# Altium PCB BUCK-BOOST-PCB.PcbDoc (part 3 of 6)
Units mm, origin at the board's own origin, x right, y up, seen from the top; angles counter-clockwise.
Board outline 99.9 x 67.48 mm, 4 copper layers (Top Layer, POWER, GND, Bottom Layer); 181 components, 110 nets, 560 pads, 389 vias.
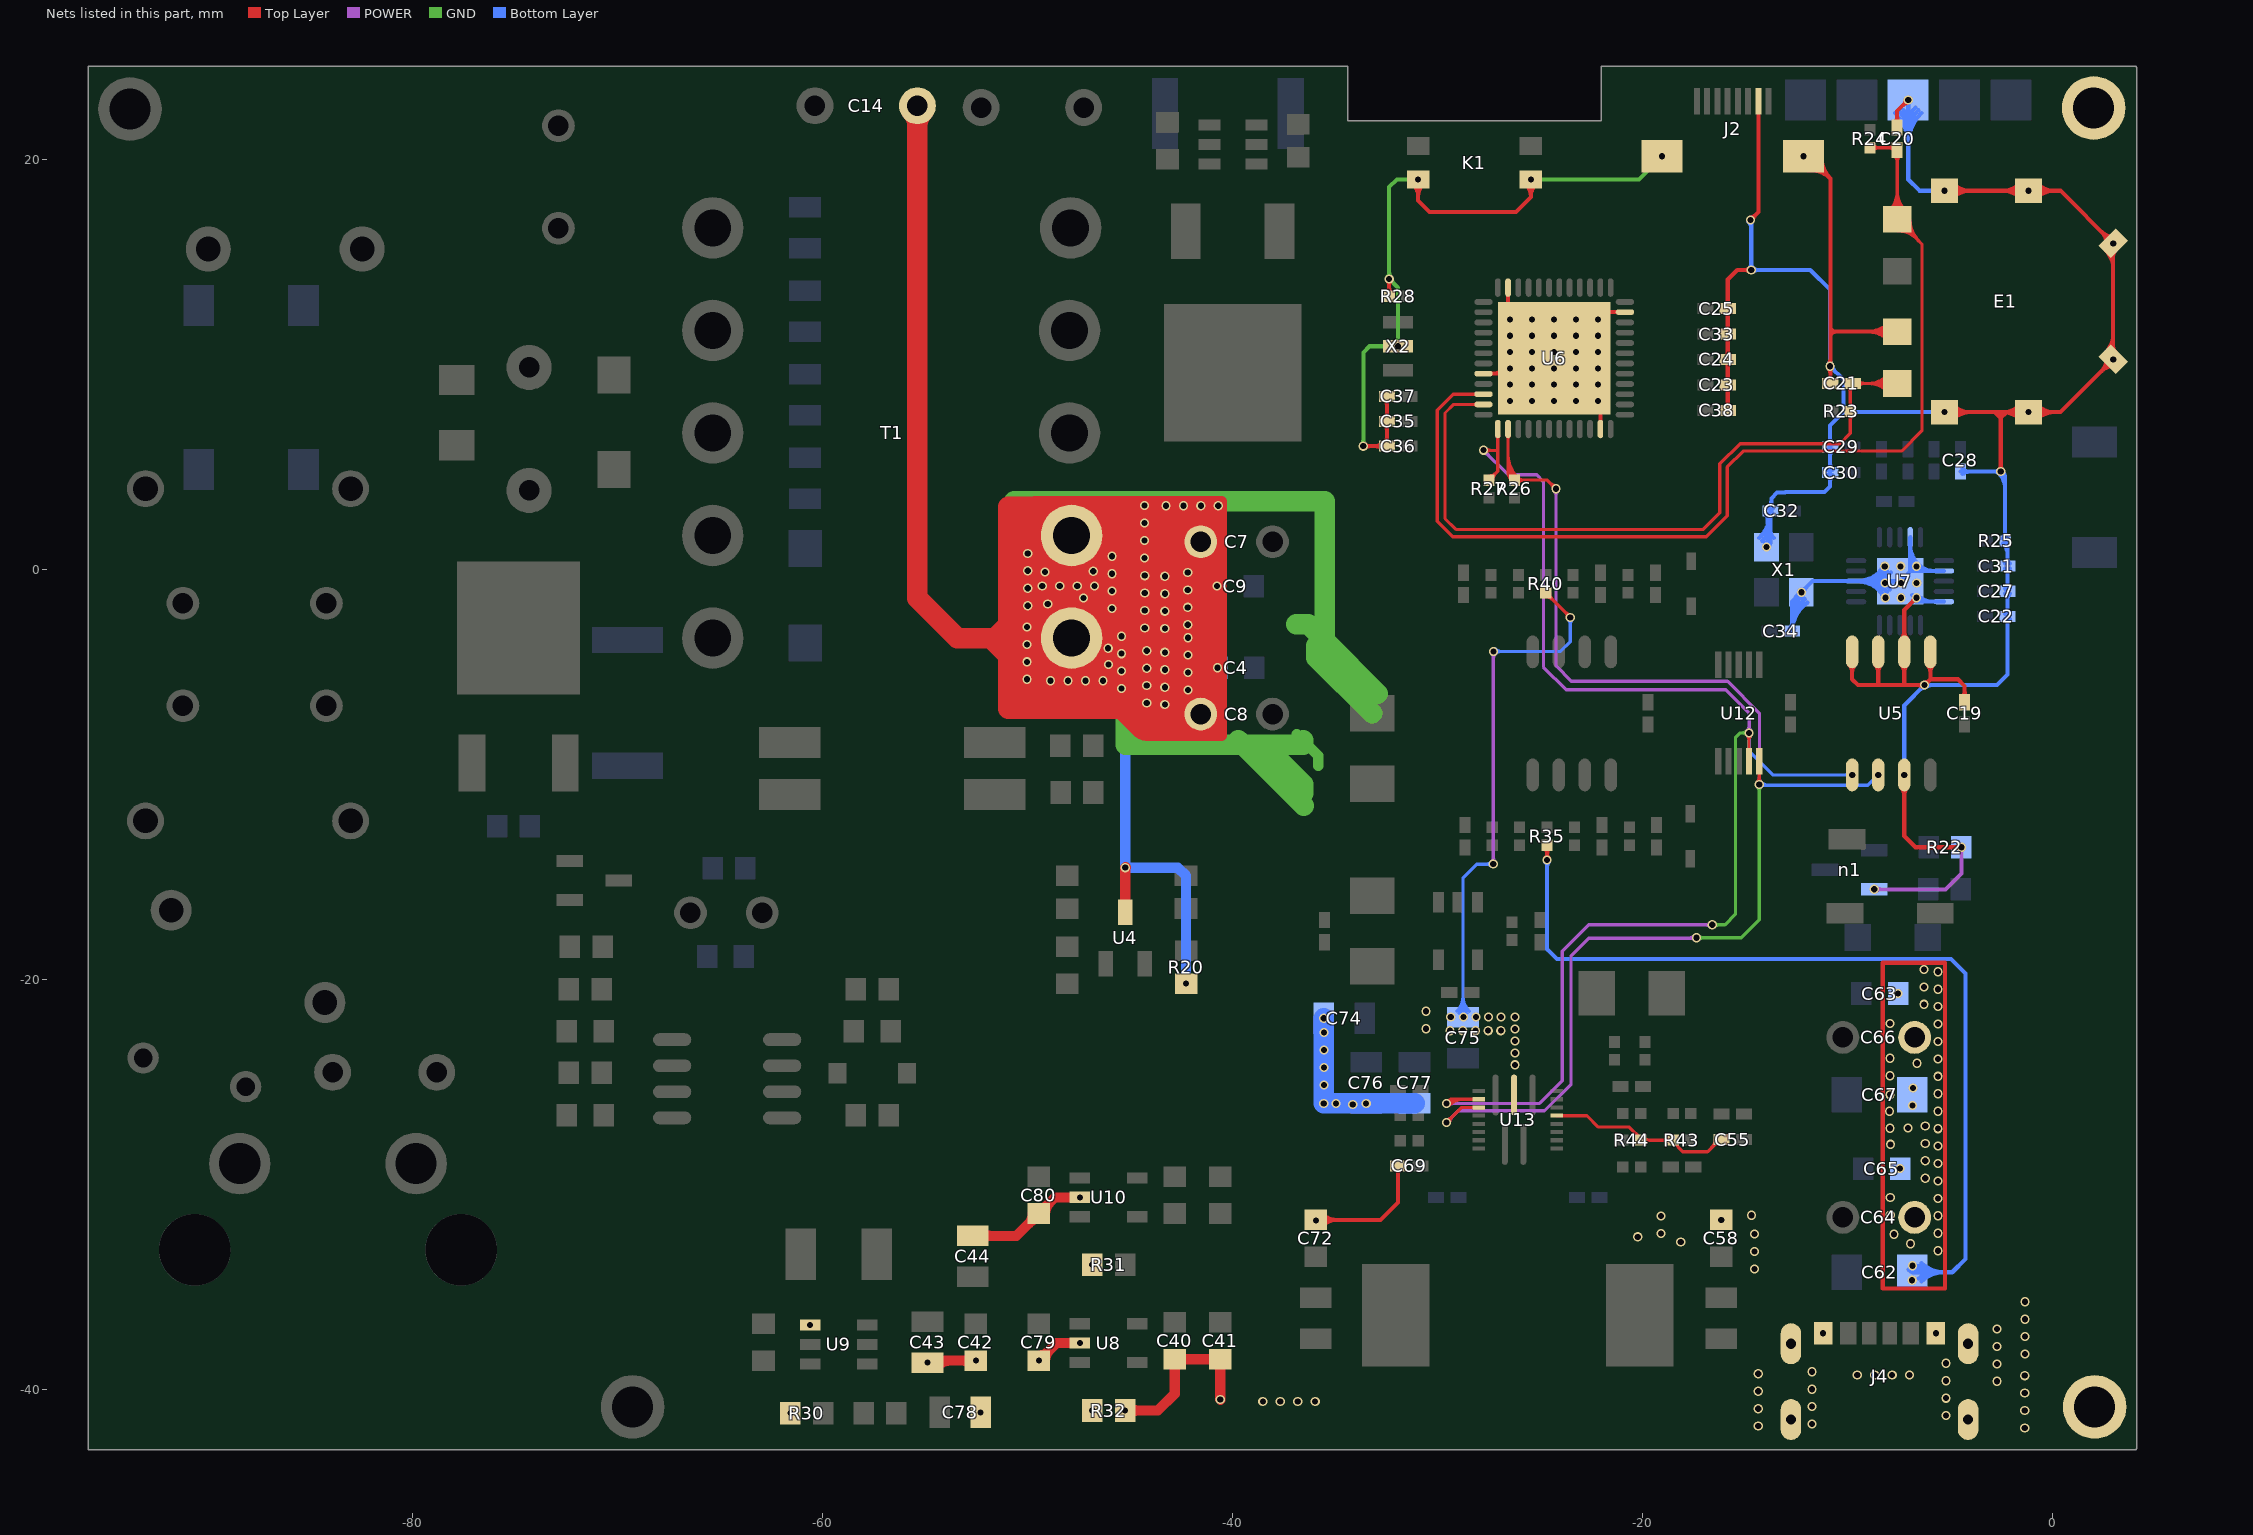
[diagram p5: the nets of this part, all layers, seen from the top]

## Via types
v1: diameter 0.45, hole 0.3, Top Layer to Bottom Layer, 389 vias

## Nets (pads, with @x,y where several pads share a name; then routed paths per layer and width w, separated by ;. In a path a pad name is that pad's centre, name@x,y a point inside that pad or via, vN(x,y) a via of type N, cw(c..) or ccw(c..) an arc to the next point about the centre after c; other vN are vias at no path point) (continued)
DGND: C19.2 C20.2 C21.2 C22.1 C23.1 C24.1 C25.1 C27.1 C28.1 C29.2 C30.2 C31.1 C32.2 C33.2 C34.2 C35.2 C36.2 C37.1 C38.2 C40.2 C41.2 E1.1 E1.2 E1.3 E1.4 E1.5 E1.6 E1.C J2.2 J2.9 J2.10 K1.3 K1.4 n1.2 pad.2 pad.@2.014,22.522 R22.2 R25.2 R28.1 R32.1 U5.1 U5.2 U5.3 U5.4 U5.7 U6.8 U6.23 U6.35 U6.47 U6.49 U7.8 U7.14 U7.17 U7.20 U7.21 X1.2 X1.4 X2.3 | length 361
  Top Layer w0.2: v1@-33.612,6.034 v1(-33.607,6.029) C36.2@-32.459,6.029 C35.2@-32.459,7.233 C37.1@-32.459,8.456 ; v1@-33.519,5.941 cw(c-33.305,5.727) -33.305,6.029 cw(c-33.305,6.331) v1@-33.519,6.117 ; C36.2@-32.705,5.909 ccw(c-32.995,5.619) -32.995,6.029 ccw(c-32.995,6.439) C36.2@-32.705,6.149 ; C36.2@-32.58,6.149 ccw(c-32.87,6.439) -32.459,6.439 ccw(c-32.049,6.439) C36.2@-32.339,6.149 ; C35.2@-32.58,7.113 cw(c-32.87,6.823) -32.459,6.823 cw(c-32.049,6.823) C35.2@-32.339,7.113 ; C35.2@-32.58,7.353 ccw(c-32.87,7.643) -32.459,7.643 ccw(c-32.049,7.643) C35.2@-32.339,7.353 ; C37.1@-32.58,8.336 cw(c-32.87,8.046) -32.459,8.046 cw(c-32.049,8.046) C37.1@-32.339,8.336 ; R28.1@-32.467,13.459 ccw(c-32.758,13.75) -32.347,13.75 ccw(c-31.937,13.75) R28.1@-32.227,13.459 ; v1@-32.436,14.099 cw(c-32.649,13.886) -32.347,13.886 cw(c-32.045,13.886) v1@-32.259,14.099 ; v1@-32.361,14.201 v1(-32.347,14.187) R28.1@-32.347,13.339 ; K1.3@-31.173,18.801 cw(c-31.75,18.225) -30.935,18.225 cw(c-30.12,18.225) K1.3@-30.696,18.801 ; K1.3@-31.023,18.952 cw(c-31.237,18.738) -30.935,18.738 cw(c-30.633,18.738) K1.3@-30.846,18.952 ; v1(-30.935,19.04) -30.935,18.014 -30.375,17.454 -26.161,17.454 -25.435,18.18 v1(-25.435,19.04) ; U6.8@-27.746,9.564 -25.046,9.564 U6.49@-24.296,10.314 ; U6.8@-27.385,9.564 ccw(c-27.385,10.755) U6.49@-26.544,9.913 ; U6.49@-26.903,9.564 ccw(c-26.903,10.272) U6.49@-26.402,9.771 ; U6.47@-26.547,13.763 U6.49@-26.547,12.564 ; U6.49@-26.545,12.298 ccw(c-26.681,12.43) U6.49@-26.547,12.564 ; U6.49@-26.508,9.771 ccw(c-26.008,10.272) U6.49@-26.008,9.564 ; U6.49@-26.455,12.086 cw(c-26.455,11.153) U6.49@-25.796,11.813 ; U6.49@-26.455,12.286 cw(c-26.455,11.836) U6.49@-26.137,12.154 ; U6.49@-26.367,9.913 ccw(c-25.525,10.755) U6.49@-25.525,9.564 ; U6.49@-26.311,9.564 ccw(c-26.311,10.755) U6.49@-25.47,9.913 ; U6.49@-25.828,9.564 ccw(c-25.828,10.272) U6.49@-25.328,9.771 ; K1.4@-25.673,18.801 cw(c-26.249,18.225) -25.435,18.225 cw(c-24.62,18.225) K1.4@-25.196,18.801 ; U6.49@-25.624,11.641 ccw(c-25.381,11.884) U6.49@-25.381,11.541 ; U6.49@-25.583,11.6 cw(c-25.767,11.416) U6.49@-25.506,11.416 ; K1.4@-25.523,18.952 cw(c-25.736,18.738) -25.435,18.738 cw(c-25.133,18.738) K1.4@-25.346,18.952 ; U6.49@-25.381,11.291 cw(c-25.381,11.03) U6.49@-25.197,11.214 ; U6.49@-25.256,11.416 ccw(c-24.913,11.416) U6.49@-25.156,11.173 ; U6.49@-25.025,11.043 ccw(c-24.307,11.761) -24.307,10.745 ccw(c-24.307,11.813) U6.49@-23.552,11.058 ; U6.49@-24.745,9.865 ccw(c-25.5,10.62) U6.49@-24.432,10.62 ; U6.49@-24.684,10.701 ccw(c-24.307,11.078) -24.307,10.545 ccw(c-24.307,11.13) U6.49@-23.894,10.716 ; U6.49@-24.403,10.206 ccw(c-24.817,10.62) U6.49@-24.232,10.62 ; U6.49@-24.382,10.62 ccw(c-23.849,10.62) U6.49@-24.226,10.243 ; U6.49@-24.182,10.62 ccw(c-23.167,10.62) U6.49@-23.885,9.902 ; U6.49@-23.603,9.62 cw(c-24.194,9.029) U6.49@-23.358,9.029 ; U6.49@-23.474,11.136 ccw(c-23.753,11.416) U6.49@-23.358,11.416 ; U6.49@-23.38,11.23 cw(c-23.233,11.082) U6.49@-23.233,11.291 ; U6.49@-23.261,9.279 cw(c-23.511,9.029) U6.49@-23.158,9.029 ; U6.49@-23.233,8.904 cw(c-23.233,8.068) U6.49@-22.642,8.659 ; U6.49@-23.233,9.104 cw(c-23.233,8.751) U6.49@-22.983,9.001 ; U6.49@-23.233,11.541 ccw(c-23.233,11.936) U6.49@-22.954,11.656 ; U6.49@-23.108,11.416 cw(c-22.9,11.416) U6.49@-23.047,11.563 ; U6.49@-22.782,11.828 cw(c-22.159,11.205) U6.49@-22.159,12.086 ; U6.49@-22.47,8.487 ccw(c-22.159,8.799) U6.49@-22.159,8.358 ; U6.49@-22.44,12.17 cw(c-22.159,11.888) U6.49@-22.159,12.286 ; U6.49@-22.247,8.145 cw(c-22.734,7.659) U6.49@-22.046,7.659 ; U6.49@-22.061,12.289 cw(c-21.9,12.418) U6.49@-22.046,12.564 ; U6.23@-22.046,6.864 -22.046,8.063 U6.49@-24.296,10.314 ; U6.35@-20.847,12.564 U6.49@-22.046,12.564 ; C38.2@-15.952,7.898 ccw(c-16.243,8.188) -15.832,8.188 ccw(c-15.422,8.188) C38.2@-15.712,7.898 ; C23.1@-15.952,8.897 cw(c-16.243,8.607) -15.832,8.607 cw(c-15.422,8.607) C23.1@-15.712,8.897 ; C23.1@-15.952,9.138 ccw(c-16.243,9.428) -15.832,9.428 ccw(c-15.422,9.428) C23.1@-15.712,9.138 ; C24.1@-15.952,10.137 cw(c-16.243,9.847) -15.832,9.847 cw(c-15.422,9.847) C24.1@-15.712,10.137 ; C24.1@-15.952,10.378 ccw(c-16.243,10.668) -15.832,10.668 ccw(c-15.422,10.668) C24.1@-15.712,10.378 ; C33.2@-15.952,11.377 cw(c-16.243,11.087) -15.832,11.087 cw(c-15.422,11.087) C33.2@-15.712,11.377 ; C33.2@-15.952,11.618 ccw(c-16.243,11.908) -15.832,11.908 ccw(c-15.422,11.908) C33.2@-15.712,11.618 ; C25.1@-15.952,12.617 cw(c-16.243,12.327) -15.832,12.327 cw(c-15.422,12.327) C25.1@-15.712,12.617 ; C25.1@-15.952,12.857 ccw(c-16.243,13.148) -15.832,13.148 ccw(c-15.422,13.148) C25.1@-15.712,12.857 ; C38.2@-15.832,7.778 C23.1@-15.832,9.018 C24.1@-15.832,10.257 C33.2@-15.832,11.497 C25.1@-15.832,12.737 -15.832,14.159 -15.37,14.622 v1(-14.686,14.622) v1@-14.667,14.603 ; v1@-14.775,14.533 ccw(c-14.988,14.32) -14.988,14.622 ccw(c-14.988,14.923) v1@-14.775,14.71 ; v1(-14.729,17.055) -14.336,17.449 J2.2@-14.336,22.849 ; v1@-14.729,17.18 ccw(c-14.729,17.482) -14.516,17.268 ccw(c-14.303,17.055) v1@-14.604,17.055 ; J2.10@-12.138,20.045 cw(c-12.138,19.221) J2.10@-11.555,19.804 ; v1(-12.138,20.17) -11.921,20.17 -10.831,19.079 ; J2.10@-12.138,20.245 cw(c-12.138,19.904) J2.10@-11.896,20.145 ; J2.10@-11.901,19.672 cw(c-11.83,18.698) J2.10@-11.14,19.388 ; J2.10@-11.887,19.472 cw(c-11.787,18.123) -10.831,19.079 ; J2.10@-11.438,20.146 ccw(c-10.451,20.098) J2.10@-11.15,19.399 ; J2.10@-11.239,20.136 ccw(c-9.842,20.068) -10.831,19.079 ; C21.2@-10.951,9.21 ccw(c-11.241,9.501) -10.831,9.501 ccw(c-10.42,9.501) C21.2@-10.71,9.21 ; v1@-10.934,9.834 cw(c-11.184,9.584) -10.831,9.584 ; v1@-10.934,10.011 ccw(c-11.184,10.261) -10.831,10.261 ; C21.2@-10.831,9.09 -10.831,11.367 ; -10.831,9.657 cw(c-10.581,9.657) v1@-10.757,9.834 ; -10.831,10.188 ccw(c-10.581,10.188) v1@-10.757,10.011 ; U5.4@-9.905,-4.646 cw(c-10.247,-4.988) -9.764,-4.988 cw(c-9.281,-4.988) U5.4@-9.622,-4.646 ; U5.4@-9.764,-4.006 -9.764,-5.34 -9.478,-5.626 -8.471,-5.626 ; U5.3@-8.635,-4.646 cw(c-8.977,-4.988) -8.494,-4.988 cw(c-8.011,-4.988) U5.3@-8.352,-4.646 ; U5.3@-8.494,-4.006 -8.494,-5.603 -8.471,-5.626 ; E1.C@-8.002,11.224 ccw(c-8.941,10.285) -8.941,11.612 ccw(c-8.941,12.94) E1.C@-8.002,12.001 ; E1.C@-7.86,11.365 ccw(c-8.458,10.767) -8.458,11.612 ccw(c-8.458,12.457) E1.C@-7.86,11.86 ; C20.2@-7.689,21.809 ccw(c-7.98,22.099) -7.569,22.099 ccw(c-7.159,22.099) C20.2@-7.449,21.809 ; C20.2@-7.569,21.563 -7.569,22.369 v1(-7.031,22.907) ; E1.C@-7.563,11.612 -10.585,11.612 ; U5.7@-7.365,-10.646 cw(c-7.707,-10.987) -7.224,-10.987 cw(c-6.741,-10.987) U5.7@-7.082,-10.646 ; U5.2@-7.365,-4.646 cw(c-7.707,-4.988) -7.224,-4.988 cw(c-6.741,-4.988) U5.2@-7.082,-4.646 ; U5.2@-7.365,-3.365 ccw(c-7.707,-3.023) -7.224,-3.023 ccw(c-6.741,-3.023) U5.2@-7.082,-3.365 ; U5.7@-7.312,-10.093 cw(c-7.526,-10.307) -7.224,-10.307 cw(c-6.922,-10.307) U5.7@-7.135,-10.093 ; v1(-7.224,-10.005) -7.224,-12.981 -6.671,-13.533 v1(-4.439,-13.533) ; v1@-7.156,22.907 cw(c-7.457,22.907) -7.244,22.694 cw(c-7.031,22.48) v1@-7.031,22.782 ; v1@-6.751,-1.361 cw(c-7.052,-1.361) -6.839,-1.575 cw(c-6.626,-1.788) v1@-6.626,-1.486 ; v1(-6.626,-1.361) -7.224,-1.96 U5.2@-7.224,-4.006 -7.224,-5.594 -7.256,-5.626 ; v1@-6.328,-5.714 ccw(c-6.541,-5.928) -6.541,-5.626 ccw(c-6.541,-5.324) v1@-6.328,-5.538 ; v1@-6.24,-5.501 ccw(c-6.24,-5.199) -6.026,-5.413 ccw(c-5.813,-5.626) v1@-6.115,-5.626 ; U5.1@-6.095,-4.646 cw(c-6.437,-4.988) -5.954,-4.988 cw(c-5.471,-4.988) U5.1@-5.812,-4.646 ; U5.1@-5.954,-4.006 -5.954,-5.34 ; v1(-5.263,7.687) -2.811,7.687 ; v1(-5.263,18.487) 0.394,18.487 v1(2.965,15.916) v1(2.965,10.259) 0.394,7.687 v1(-1.163,7.687) -2.476,7.687 ; E1.1@-5.174,7.599 cw(c-4.961,7.386) -4.961,7.687 cw(c-4.961,7.989) E1.1@-5.174,7.776 ; E1.6@-5.174,18.399 cw(c-4.961,18.186) -4.961,18.487 cw(c-4.961,18.789) E1.6@-5.174,18.576 ; E1.1@-5.001,7.475 cw(c-4.489,6.963) -4.489,7.687 cw(c-4.488,8.412) E1.1@-5.001,7.9 ; E1.6@-5.001,18.275 cw(c-4.488,17.763) -4.488,18.487 cw(c-4.488,19.212) E1.6@-5.001,18.7 ; E1.1@-4.859,7.334 cw(c-4.006,6.48) -4.006,7.687 cw(c-4.006,8.895) E1.1@-4.859,8.041 ; E1.6@-4.859,18.134 cw(c-4.006,17.28) -4.006,18.487 cw(c-4.006,19.695) E1.6@-4.859,18.841 ; v1@-4.527,-13.621 ccw(c-4.74,-13.835) -4.74,-13.533 ccw(c-4.74,-13.231) v1@-4.527,-13.445 ; C19.2@-4.399,-6.215 ccw(c-4.689,-5.925) -4.279,-5.925 ccw(c-3.868,-5.925) C19.2@-4.158,-6.215 ; C19.2@-4.279,-6.46 -4.279,-5.67 -4.609,-5.34 -5.954,-5.34 ; v1@-2.609,4.876 ccw(c-2.823,5.09) -2.521,5.09 ccw(c-2.219,5.09) v1@-2.432,4.876 ; v1(-2.521,4.788) -2.521,7.398 ; -2.202,7.668 -2.251,7.668 -2.521,7.398 ; E1.2@-1.566,7.334 ccw(c-2.42,6.48) -2.42,7.687 ccw(c-2.42,8.894) E1.2@-1.566,8.041 ; E1.5@-1.566,18.134 ccw(c-2.42,17.28) -2.42,18.487 ccw(c-2.42,19.695) E1.5@-1.566,18.841 ; E1.2@-1.425,7.475 ccw(c-1.937,6.963) -1.937,7.687 ccw(c-1.937,8.412) E1.2@-1.425,7.9 ; E1.5@-1.425,18.275 ccw(c-1.937,17.763) -1.937,18.487 ccw(c-1.937,19.212) E1.5@-1.425,18.7 ; E1.2@-1.251,7.599 ccw(c-1.465,7.386) -1.465,7.687 ccw(c-1.465,7.989) E1.2@-1.251,7.776 ; E1.5@-1.251,18.399 ccw(c-1.465,18.186) -1.465,18.487 ccw(c-1.465,18.789) E1.5@-1.251,18.576 ; E1.2@-1.074,7.599 cw(c-0.861,7.386) -0.861,7.687 cw(c-0.861,7.989) E1.2@-1.074,7.776 ; E1.5@-1.074,18.399 cw(c-0.861,18.186) -0.861,18.487 cw(c-0.861,18.789) E1.5@-1.074,18.576 ; E1.2@-0.901,7.475 cw(c-0.389,6.963) -0.389,7.687 cw(c-0.389,8.412) E1.2@-0.901,7.9 ; E1.5@-0.901,18.275 cw(c-0.389,17.763) -0.389,18.487 cw(c-0.389,19.212) E1.5@-0.901,18.7 ; E1.2@-0.759,7.334 cw(c0.094,6.48) 0.094,7.687 cw(c0.094,8.894) E1.2@-0.759,8.041 ; E1.5@-0.759,18.134 cw(c0.094,17.28) 0.094,18.487 cw(c0.094,19.695) E1.5@-0.759,18.841 ; E1.3@2.612,10.613 ccw(c1.758,11.466) 2.965,11.466 ; E1.4@2.612,15.562 cw(c1.758,14.709) 2.965,14.709 ; E1.3@2.64,10.259 cw(c1.856,10.259) 2.411,9.704 cw(c2.965,9.149) E1.3@2.965,9.934 ; E1.4@2.64,15.916 ccw(c1.856,15.916) 2.411,16.471 ccw(c2.965,17.025) E1.4@2.965,16.241 ; E1.3@2.753,10.471 ccw(c2.241,10.983) 2.965,10.983 ; E1.4@2.753,15.704 cw(c2.241,15.191) 2.965,15.191 ; E1.3@2.84,10.259 cw(c2.539,10.259) 2.752,10.046 cw(c2.965,9.832) E1.3@2.965,10.134 ; E1.4@2.84,15.916 ccw(c2.539,15.916) 2.752,16.129 ccw(c2.965,16.342) E1.4@2.965,16.041 ; E1.3@2.877,10.348 ccw(c2.664,10.561) 2.965,10.561 ccw(c3.267,10.561) E1.3@3.054,10.348 ; E1.4@2.877,15.827 cw(c2.664,15.614) 2.965,15.614 cw(c3.267,15.614) E1.4@3.054,15.827 ; 2.965,10.869 ccw(c3.328,10.869) E1.3@3.072,10.613 ; 2.965,15.306 cw(c3.328,15.306) E1.4@3.072,15.562 ; U6.49@-26.547,12.564 U6.49@-24.296,10.314 ; U6.49@-24.296,10.314 U6.49@-22.046,12.564 ; -10.831,11.367 cw(c-10.585,11.367) -10.585,11.612 ; -10.831,11.367 -10.831,11.612 ; -10.831,11.612 -10.831,11.858 ; -10.831,11.612 -10.585,11.612 ; -10.831,11.858 ccw(c-10.585,11.858) -10.585,11.612 ; -10.831,11.858 -10.831,19.079 ; -8.471,-5.626 -7.256,-5.626 ; -7.256,-5.626 v1(-6.24,-5.626) -5.954,-5.34 ; -2.811,7.687 -2.521,7.398 ; -2.811,7.687 -2.476,7.687 ; -2.521,7.398 -2.521,7.643 -2.476,7.687
  Top Layer w0.5: R32.1@-45.25,-41.019 ccw(c-45.034,-40.866) R32.1@-44.902,-41.095 ; R32.1@-45.25,-40.99 cw(c-45.034,-41.143) R32.1@-44.902,-40.914 ; v1(-45.229,-41.004) -43.626,-41.004 -42.807,-40.186 C40.2@-42.807,-38.503 C41.2@-40.587,-38.503 v1(-40.587,-40.463) v1@-40.568,-40.483 ; R32.1@-45.052,-41.181 cw(c-44.625,-41.609) -44.625,-41.004 cw(c-44.625,-40.4) R32.1@-45.052,-40.827 ; C40.2@-42.984,-38.68 cw(c-43.411,-39.107) -42.807,-39.107 cw(c-42.203,-39.107) C40.2@-42.63,-38.68 ; C40.2@-42.579,-38.68 cw(c-42.152,-39.107) -42.152,-38.503 cw(c-42.152,-37.898) C40.2@-42.579,-38.326 ; C41.2@-40.815,-38.68 ccw(c-41.242,-39.107) -41.242,-38.503 ccw(c-41.242,-37.898) C41.2@-40.815,-38.326 ; C41.2@-40.764,-38.68 cw(c-41.192,-39.107) -40.587,-39.107 cw(c-39.983,-39.107) C41.2@-40.41,-38.68
  POWER w0.2: v1(-8.689,-15.584) -5.215,-15.584 -4.439,-14.808 v1(-4.439,-13.533) ; v1@-8.601,-15.672 cw(c-8.388,-15.886) -8.388,-15.584 cw(c-8.388,-15.282) v1@-8.601,-15.496 ; v1@-4.527,-13.621 cw(c-4.74,-13.835) -4.439,-13.835 cw(c-4.137,-13.835) v1@-4.35,-13.621
  GND w0.2: v1@-33.695,6.117 ccw(c-33.909,6.331) -33.607,6.331 ccw(c-33.305,6.331) v1@-33.519,6.117 ; v1(-33.607,6.029) -33.607,10.593 -33.298,10.902 v1(-31.914,10.902) -31.914,13.755 v1(-32.347,14.187) -32.347,18.664 -31.971,19.04 v1(-30.935,19.04) ; v1@-32.436,14.276 ccw(c-32.649,14.489) -32.347,14.489 ccw(c-32.045,14.489) v1@-32.259,14.276 ; v1@-32.347,14.062 cw(c-32.347,13.761) -32.134,13.974 cw(c-31.92,14.187) v1@-32.222,14.187 ; v1@-32.003,10.814 ccw(c-32.216,10.6) -32.216,10.902 ccw(c-32.216,11.204) -32.003,10.99 ccw(c-32.216,11.204) -31.914,11.204 ccw(c-31.613,11.204) v1@-31.826,10.99 ; v1@-31.023,18.952 ccw(c-31.237,18.738) -31.237,19.04 ccw(c-31.237,19.342) v1@-31.023,19.128 ; v1(-25.435,19.04) -20.168,19.04 v1(-19.038,20.17) ; v1@-25.346,18.952 cw(c-25.133,18.738) -25.133,19.04 cw(c-25.133,19.342) v1@-25.346,19.128 ; v1@-19.163,20.17 cw(c-19.464,20.17) -19.251,19.957 cw(c-19.038,19.743) v1@-19.038,20.045
  Bottom Layer w0.2: v1@-14.818,16.967 cw(c-15.135,16.649) -14.686,16.649 ; v1@-14.775,14.71 ccw(c-14.988,14.923) -14.686,14.923 ccw(c-14.385,14.923) -14.598,14.71 ccw(c-14.385,14.923) -14.385,14.622 ccw(c-14.385,14.32) v1@-14.598,14.533 ; v1(-14.729,17.055) -14.686,17.012 v1(-14.686,14.622) -11.808,14.622 -10.846,13.659 v1(-10.846,9.923) -10.193,9.27 -10.193,7.687 ; X1.2@-14.294,1.558 ccw(c-15.605,2.87) C32.2@-13.75,2.87 ; X1.2@-14.153,1.417 ccw(c-15.123,2.388) -13.75,2.388 ; X1.2@-14.029,1.193 ccw(c-14.703,1.866) -13.75,1.866 ; X1.2@-14.012,1.275 ccw(c-14.641,1.905) -13.75,1.905 ; C32.2@-14.01,2.766 cw(c-14.484,2.396) -13.899,2.254 ; v1(-13.941,1.104) -13.75,1.295 C32.2@-13.75,2.87 ; X1.2@-13.888,1.051 ccw(c-14.22,1.383) X1.2@-13.75,1.383 ; C32.2@-13.871,2.75 cw(c-14.161,2.46) -13.75,2.46 cw(c-13.34,2.46) C32.2@-13.63,2.75 ; C32.2@-13.871,2.99 ccw(c-14.268,3.388) -13.706,3.388 ; X1.2@-13.831,1.163 cw(c-13.432,1.375) X1.2@-13.823,1.601 ; -13.75,1.951 ccw(c-13.194,1.951) X1.2@-13.587,1.558 ; -13.706,3.173 ccw(c-13.448,3.173) C32.2@-13.63,2.99 ; C34.2@-12.815,-2.874 ccw(c-13.105,-2.584) -12.694,-2.584 ccw(c-12.284,-2.584) C34.2@-12.574,-2.874 ; C34.2@-12.694,-3.051 cw(c-10.913,-3.051) X1.4@-11.95,-1.602 ; C34.2@-12.694,-2.995 -12.694,-1.549 v1(-12.241,-1.096) -11.702,-0.557 U7.8@-9.577,-0.557 ; -12.694,-2.662 cw(c-11.192,-2.662) X1.4@-12.066,-1.44 ; -12.694,-2.273 cw(c-11.47,-2.273) X1.4@-12.183,-1.277 ; -12.694,-1.883 cw(c-11.749,-1.883) X1.4@-12.299,-1.114 ; X1.4@-12.554,-1.729 ccw(c-13.21,-1.191) X1.4@-12.365,-1.108 ; X1.4@-12.509,-1.37 cw(c-12.188,-1.633) X1.4@-12.229,-1.22 ; X1.4@-12.366,-1.096 cw(c-12.668,-1.096) -12.454,-1.309 cw(c-12.241,-1.523) X1.4@-12.241,-1.221 ; X1.4@-12.248,-1.356 ccw(c-12.53,-1.124) X1.4@-12.166,-1.088 ; X1.4@-12.241,-0.971 ccw(c-12.241,-0.669) -12.028,-0.882 ccw(c-11.814,-1.096) X1.4@-12.116,-1.096 ; C30.2@-10.959,4.62 cw(c-11.249,4.33) -10.839,4.33 cw(c-10.428,4.33) C30.2@-10.718,4.62 ; C30.2@-10.959,4.86 ccw(c-11.249,5.151) -10.839,5.151 ccw(c-10.428,5.151) C30.2@-10.718,4.86 ; C29.2@-10.959,5.875 cw(c-11.249,5.584) -10.839,5.584 cw(c-10.428,5.584) C29.2@-10.718,5.875 ; C29.2@-10.959,6.115 ccw(c-11.249,6.405) -10.839,6.405 ccw(c-10.428,6.405) C29.2@-10.718,6.115 ; v1@-10.934,10.011 ccw(c-11.148,10.224) -10.846,10.224 ccw(c-10.544,10.224) v1@-10.757,10.011 ; v1@-10.846,9.798 cw(c-10.846,9.496) -10.632,9.709 cw(c-10.419,9.923) v1@-10.721,9.923 ; U7.8@-9.163,-0.557 cw(c-9.163,-1.945) U7.21@-8.075,-1.082 ; U7.8@-9.155,-0.557 ccw(c-9.155,0.848) U7.21@-8.067,-0.041 ; -8.749,-0.557 cw(c-8.749,-1.617) U7.21@-7.918,-0.958 ; -8.733,-0.557 ccw(c-8.733,0.503) U7.21@-7.913,-0.167 ; -8.726,-0.666 ccw(c-8.565,-0.282) U7.21@-8.253,-0.558 ; -8.666,-0.557 cw(c-8.666,-1.148) U7.21@-8.248,-0.73 ; -8.623,-0.593 ccw(c-8.488,-0.13) U7.21@-8.227,-0.536 ; -8.603,-0.459 ccw(c-9.084,0.157) U7.21@-8.303,0.166 ; U7.21@-8.468,-0.774 ccw(c-8.344,-0.478) U7.21@-8.104,-0.691 ; U7.21@-8.465,-0.101 ccw(c-8.728,0.239) U7.21@-8.301,0.184 ; U7.21@-8.456,-1.018 cw(c-8.792,-1.418) U7.21@-8.272,-1.372 ; U7.21@-8.285,-0.21 ccw(c-8.576,0.163) U7.21@-8.103,0.169 ; U7.21@-8.233,-0.658 cw(c-7.91,-0.583) U7.21@-8.112,-0.321 ; U7.21@-8.231,-1.206 ccw(c-9.577,-2.274) U7.8@-9.577,-0.557 ; U7.21@-8.222,0.086 cw(c-9.577,1.192) U7.8@-9.577,-0.557 ; U7.21@-8.071,-0.73 cw(c-7.653,-1.148) U7.21@-7.653,-0.557 ; U7.21@-8.038,-0.613 cw(c-7.577,-0.506) U7.21@-7.866,-0.131 ; U7.21@-8.035,-0.652 ccw(c-7.661,-0.684) U7.21@-7.913,-0.963 ; U7.21@-7.896,-0.557 cw(c-7.896,-1.148) U7.21@-7.479,-0.73 ; pad.2@-7.667,22.271 cw(c-9.204,20.734) -7.031,20.734 cw(c-4.858,20.734) pad.2@-6.394,22.271 ; pad.2@-7.526,22.412 cw(c-8.721,21.217) -7.031,21.217 cw(c-5.341,21.217) pad.2@-6.536,22.412 ; pad.2@-7.384,22.554 cw(c-8.238,21.7) -7.031,21.7 cw(c-5.824,21.7) pad.2@-6.677,22.554 ; v1@-7.312,-9.917 ccw(c-7.526,-9.703) -7.224,-9.703 ccw(c-6.922,-9.703) v1@-7.135,-9.917 ; U7.21@-7.265,-0.641 cw(c-6.699,-0.641) U7.21@-7.099,-0.241 ; v1(-7.224,-10.005) -7.224,-6.61 v1(-6.24,-5.626) -2.699,-5.626 -2.189,-5.117 C22.1@-2.189,-2.273 C27.1@-2.189,-1.047 C31.1@-2.189,0.178 -2.189,1.292 R25.2@-2.301,1.404 -2.301,4.569 v1(-2.521,4.788) C28.1@-4.489,4.788 ; pad.2@-7.119,22.819 cw(c-7.332,22.605) -7.031,22.605 cw(c-6.729,22.605) pad.2@-6.942,22.819 ; v1(-7.031,22.907) -7.031,19.042 -6.476,18.487 v1(-5.263,18.487) ; U7.21@-6.934,0.257 ccw(c-6.532,0.257) -6.816,-0.027 ccw(c-6.744,0.045) U7.21@-6.744,-0.057 ; -6.934,0.74 ccw(c-6.05,0.74) -6.675,0.115 ccw(c-6.261,0.528) -6.261,-0.057 ; U7.14@-6.934,1.223 ccw(c-5.567,1.223) -6.533,0.256 ccw(c-5.779,1.011) U7.17@-5.779,-0.057 ; U7.14@-6.934,1.586 -6.934,-0.038 U7.21@-6.915,-0.057 ; U7.21@-6.834,-1.236 U7.21@-6.656,-1.414 ; U7.21@-6.679,-1.414 ccw(c-6.335,-1.071) U7.21@-6.335,-1.557 ; U7.21@-6.656,-1.557 U7.20@-5.291,-1.557 ; U7.21@-6.537,-1.273 ccw(c-5.853,-0.588) -5.853,-1.557 ; v1@-6.365,-5.626 cw(c-6.666,-5.626) -6.453,-5.839 cw(c-6.24,-6.053) v1@-6.24,-5.751 ; v1@-6.151,-5.714 cw(c-5.938,-5.928) -5.938,-5.626 cw(c-5.938,-5.324) v1@-6.151,-5.538 ; v1@-5.351,7.599 ccw(c-5.565,7.386) -5.565,7.687 ccw(c-5.565,7.989) v1@-5.351,7.776 ; v1@-5.351,18.399 ccw(c-5.565,18.186) -5.565,18.487 ccw(c-5.565,18.789) v1@-5.351,18.576 ; U7.17@-5.291,-0.057 U7.21@-6.915,-0.057 ; v1(-5.263,7.687) -10.193,7.687 ; C28.1@-4.369,4.668 cw(c-4.079,4.377) -4.079,4.788 cw(c-4.079,5.198) C28.1@-4.369,4.908 ; v1@-2.609,4.876 cw(c-2.823,5.09) -2.823,4.788 cw(c-2.823,4.486) -2.609,4.699 cw(c-3.352,3.957) -2.301,3.957 ; v1@-2.468,4.841 cw(c-2.869,4.439) -2.301,4.439 ; R25.2@-2.422,1.524 ccw(c-2.712,1.814) -2.301,1.814 ccw(c-1.891,1.814) R25.2@-2.181,1.524 ; R25.2@-2.409,1.284 cw(c-2.939,0.753) -2.189,0.753 ; C22.1@-2.309,-2.393 cw(c-2.6,-2.683) -2.189,-2.683 cw(c-1.779,-2.683) C22.1@-2.069,-2.393 ; C22.1@-2.309,-2.153 ccw(c-2.6,-1.862) -2.189,-1.862 ccw(c-1.779,-1.862) C22.1@-2.069,-2.153 ; C27.1@-2.309,-1.168 cw(c-2.6,-1.458) -2.189,-1.458 cw(c-1.779,-1.458) C27.1@-2.069,-1.168 ; C27.1@-2.309,-0.927 ccw(c-2.6,-0.637) -2.189,-0.637 ccw(c-1.779,-0.637) C27.1@-2.069,-0.927 ; C31.1@-2.309,0.058 cw(c-2.6,-0.232) -2.189,-0.232 cw(c-1.779,-0.232) C31.1@-2.069,0.058 ; C31.1@-2.309,0.298 ccw(c-2.6,0.589) -2.189,0.589 ccw(c-1.779,0.589) C31.1@-2.069,0.298 ; C32.2@-13.75,2.87 -13.706,2.915 -13.706,3.475 -13.421,3.759 -13.051,3.759 -13.025,3.785 -11.111,3.785 -10.839,4.057 C30.2@-10.839,4.74 C29.2@-10.839,5.995 -10.839,7.042 -10.193,7.687 ; U7.8@-9.577,-0.557 -7.434,-0.557 U7.21@-7.424,-0.566 U7.21@-6.915,-0.057
  other v1: -8.147,-1.361 -7.386,-1.361 -8.16,-0.641 -7.39,-0.641 -6.621,-0.641 -8.178,0.168 -7.4,0.168 -6.622,0.168 -26.455,8.233 -25.381,8.233 -24.307,8.233 -23.233,8.233 -22.159,8.233 -26.455,9.029 -25.381,9.029 -24.307,9.029 -23.233,9.029 -22.159,9.029 -26.455,9.825 -25.381,9.825 -24.307,9.825 -23.233,9.825 -22.159,9.825 -26.455,10.62 -25.381,10.62 -24.307,10.62 -23.233,10.62 -22.159,10.62 -26.455,11.416 -25.381,11.416 -24.307,11.416 -23.233,11.416 -22.159,11.416 -26.455,12.211 -25.381,12.211 -24.307,12.211 -23.233,12.211 -22.159,12.211 -1.163,18.487
EN-A: C20.1 E1.A R24.1 U6.10 | length 61.4
  Top Layer w0.16: U6.10@-28.098,8.521 ccw(c-28.201,8.419) -28.201,8.564 ccw(c-28.201,8.708) U6.10@-28.098,8.606 ; U6.10@-27.746,8.564 -29.215,8.564 -30.004,7.775 -30.004,2.369 -29.241,1.606 -16.883,1.606 -15.861,2.628 -15.861,5.015 -15.086,5.791 -7.358,5.791 -6.364,6.784 -6.364,15.889 E1.A@-7.563,17.087 ; R24.1@-8.898,20.586 -7.681,20.586 C20.1@-7.569,20.473 E1.A@-7.569,17.094 ; R24.1@-8.763,20.451 cw(c-8.439,20.127) -8.439,20.586 cw(c-8.439,21.044) R24.1@-8.763,20.72 ; -8.059,20.586 ccw(c-8.059,21.088) C20.1@-7.704,20.733 ; -7.997,20.586 cw(c-7.997,20.171) C20.1@-7.704,20.464 ; E1.A@-7.966,17.49 ccw(c-8.924,18.448) -7.569,18.448 ; E1.A@-7.853,17.377 ccw(c-8.537,18.062) -7.569,18.062 ; C20.1@-7.704,20.214 cw(c-8.028,19.89) -7.569,19.89 cw(c-7.11,19.89) C20.1@-7.435,20.214 ; -7.569,18.093 ccw(c-6.558,18.093) E1.A@-7.273,17.377 ; -7.569,18.479 ccw(c-6.171,18.479) E1.A@-7.16,17.49 ; E1.A@-7.513,16.517 cw(c-7.513,15.262) -6.625,16.15 ; E1.A@-7.513,16.677 cw(c-7.513,15.808) -6.898,16.423 ; E1.A@-7.263,17.087 ccw(c-6.539,17.087) E1.A@-7.051,16.575 ; E1.A@-7.103,17.087 ccw(c-5.992,17.087) -6.778,16.302 ; E1.A@-6.943,17.087 ccw(c-5.446,17.087) -6.504,16.029
EN-B: C21.1 E1.B R23.1 U6.11 | length 42
  Top Layer w0.16: U6.11@-28.098,8.021 ccw(c-28.201,7.918) -28.201,8.063 ccw(c-28.201,8.208) U6.11@-28.098,8.106 ; U6.11@-27.746,8.063 -29.206,8.063 -29.624,7.645 -29.624,2.498 -29.092,1.966 -17.032,1.966 -16.221,2.777 -16.221,5.164 -15.235,6.151 -10.358,6.151 -9.853,6.656 R23.1@-9.853,7.724 -9.853,8.978 C21.1@-9.741,9.09 E1.B@-7.566,9.09 ; C21.1@-10,8.956 cw(c-10.355,8.601) -9.853,8.601 ; R23.1@-9.987,7.589 cw(c-10.311,7.265) -9.853,7.265 cw(c-9.394,7.265) R23.1@-9.718,7.589 ; R23.1@-9.987,7.858 ccw(c-10.311,8.182) -9.853,8.182 ccw(c-9.394,8.182) R23.1@-9.718,7.858 ; -9.853,8.662 cw(c-9.438,8.662) C21.1@-9.731,8.956 ; C21.1@-9.481,8.956 cw(c-9.157,8.632) -9.157,9.09 cw(c-9.157,9.549) C21.1@-9.481,9.225 ; -8.996,9.09 cw(c-8.996,7.705) E1.B@-8.016,8.684 ; -8.982,9.09 ccw(c-8.982,10.457) E1.B@-8.016,9.49 ; -8.609,9.09 cw(c-8.609,8.091) E1.B@-7.903,8.798 ; -8.596,9.09 ccw(c-8.596,10.071) E1.B@-7.903,9.377
FB: C55.1 R43.2 R44.1 U13.18 | length 11.3
  Top Layer w0.16: U13.18@-24.178,-26.622 -22.698,-26.622 -22.139,-27.182 -20.638,-27.182 -20.083,-27.737 R44.1@-20.083,-27.82 R43.2@-18.497,-27.82 -18.497,-27.903 -18.022,-28.378 -16.819,-28.378 -16.232,-27.791 C55.1@-16.138,-27.791 ; R44.1@-19.935,-27.954 cw(c-19.611,-28.279) -19.611,-27.82 cw(c-19.611,-27.361) R44.1@-19.935,-27.686 ; R43.2@-18.644,-27.954 ccw(c-18.969,-28.279) -18.969,-27.82 ccw(c-18.969,-27.361) R43.2@-18.644,-27.686 ; -16.609,-28.169 ccw(c-16.987,-27.791) C55.1@-16.453,-27.791 ; -16.534,-28.094 cw(c-16.263,-28.365) C55.1@-16.263,-27.981
GND: C4.2 C7.2 C8.2 C9.2 C14.1 C42.2 C43.2 C44.2 C58.2 C62.2 C63.2 C64.2 C65.1 C66.2 C67.1 C69.1 C72.2 C74.1 C75.1 C76.1 C77.1 C78.2 C79.2 C80.2 J4.7 J4.A12 J4.B12 pad.@2.062,-40.829 R20.1 R30.2 R31.2 R32.2 R35.2 R40.2 T1.6 T1.7 U4.3 U8.2 U9.1 U10.2 U13.2 | length 527.7
  Top Layer w0.16: R40.2@-24.709,-1.324 cw(c-24.709,-1.814) -24.363,-1.468 ; R40.2@-24.709,-1.121 -23.513,-2.318 v1(-23.513,-2.325) ; R40.2@-24.519,-1.134 ccw(c-24.092,-1.134) -24.394,-1.437 ; -23.766,-2.065 cw(c-24.026,-2.325) v1@-23.658,-2.325 ; -23.748,-2.083 ccw(c-23.513,-1.848) v1@-23.513,-2.18
  Top Layer w0.2: C72.2@-35.923,-31.711 C72.2@-35.688,-31.711 ; C72.2@-35.909,-31.49 C72.2@-35.688,-31.711 ; C72.2@-35.835,-31.827 cw(c-35.554,-32.108) C72.2@-35.554,-31.711 ; C72.2@-35.66,-31.738 C72.2@-35.688,-31.711 ; C72.2@-35.589,-31.994 cw(c-34.906,-32.677) -34.906,-31.711 cw(c-34.906,-30.744) C72.2@-35.589,-31.427 ; C69.1@-32.033,-29.194 cw(c-32.323,-29.484) -31.913,-29.484 cw(c-31.502,-29.484) C69.1@-31.792,-29.194 ; C69.1@-31.913,-29.074 -31.913,-30.85 -32.774,-31.711 C72.2@-35.688,-31.711 ; R35.2@-24.763,-13.559 cw(c-25.054,-13.85) -24.643,-13.85 cw(c-24.233,-13.85) R35.2@-24.523,-13.559 ; v1@-24.732,-14.072 ccw(c-24.945,-13.858) -24.643,-13.858 ccw(c-24.341,-13.858) v1@-24.555,-14.072 ; v1(-24.643,-14.16) R35.2@-24.643,-13.426 ; -7.478,-35.06 -5.23,-35.06 -5.23,-19.166 -8.274,-19.166 -8.274,-35.058 -7.475,-35.058 ; C72.2@-35.835,-31.65 ccw(c-35.689,-31.504) C72.2@-35.689,-31.711 ; C72.2@-35.835,-31.65 ccw(c-35.689,-31.504) C72.2@-35.689,-31.711 ; C72.2@-35.835,-31.65 ccw(c-35.689,-31.504) C72.2@-35.689,-31.711 ; C72.2@-35.688,-31.711 ccw(c-35.688,-31.842) -35.809,-31.789 cw(c-35.688,-31.842) C72.2@-35.688,-31.711
  Top Layer w0.5: v1(-54.86,-38.667) -54.86,-38.571 v1(-52.503,-38.571) ; C43.2@-54.407,-38.843 cw(c-53.751,-39.499) -53.751,-38.571 ; C42.2@-52.731,-38.748 ccw(c-53.158,-39.176) -53.158,-38.571 ccw(c-53.158,-37.967) C42.2@-52.731,-38.394 ; C44.2@-52.657,-32.49 -50.523,-32.49 C80.2@-49.428,-31.396 -48.642,-30.609 v1(-47.431,-30.609) ; C44.2@-52.204,-32.666 cw(c-51.778,-33.092) -51.778,-32.49 cw(c-51.778,-31.889) C44.2@-52.204,-32.314 ; -49.943,-31.91 ccw(c-50.457,-31.396) C80.2@-49.73,-31.396 ; C80.2@-49.82,-31.787 cw(c-49.479,-32.128) C80.2@-49.479,-31.646 ; v1(-49.428,-38.571) -48.574,-37.716 v1(-47.431,-37.716) ; C79.2@-49.378,-38.321 ccw(c-49.378,-37.839) C79.2@-49.037,-38.18 ; C80.2@-49.378,-31.146 ccw(c-49.378,-30.664) C80.2@-49.037,-31.004 ; C79.2@-49.127,-38.571 cw(c-48.4,-38.571) -48.914,-38.057 ; C80.2@-49.127,-31.396 cw(c-48.4,-31.396) -48.914,-30.882 ; U4.3@-45.216,-16.707 v1(-45.216,-14.528) v1@-45.198,-14.51 ; C8.2@-41.925,-6.647 ccw(c-45.341,-3.231) -40.51,-3.231 ; C7.2@-41.925,0.975 cw(c-45.341,-2.441) -40.51,-2.441 ; C8.2@-41.858,-7.482 cw(c-42.313,-8.111) -41.536,-8.111 ; C7.2@-41.658,1.9 ccw(c-41.986,3.339) -40.51,3.339 ; C8.2@-41.572,-7 ccw(c-44.134,-4.438) -40.51,-4.438 ; C7.2@-41.572,1.329 cw(c-44.134,-1.233) -40.51,-1.233 ; C7.2@-41.547,1.413 ccw(c-41.843,2.712) -40.51,2.712 ; v1@-41.549,3.141 cw(c-41.07,2.662) -41.07,3.339 ; C8.2@-41.536,-7.357 -41.536,-8.111 ; -41.536,2.596 -41.536,3.339 -40.51,3.339 ; C7.2@-41.437,0.925 ccw(c-41.701,2.086) -40.51,2.086 ; C8.2@-41.218,-7.354 ccw(c-42.927,-5.645) -40.51,-5.645 ; C7.2@-41.218,1.682 cw(c-42.927,-0.026) -40.51,-0.026 ; C8.2@-41.214,-7.482 ccw(c-40.76,-8.111) -41.536,-8.111 ; -41.142,3.339 cw(c-41.142,2.662) -40.663,3.141 cw(c-41.031,2.772) -40.51,2.772 ; v1@-40.728,-0.779 cw(c-41.152,-1.26) -40.511,-1.22 ; v1@-40.726,-0.815 ccw(c-41.248,-0.294) -40.51,-0.294 ; v1@-40.726,-0.78 cw(c-41.248,-1.301) -40.51,-1.301 ; v1@-40.721,-0.808 ccw(c-41.285,-0.555) -40.708,-0.335 ; v1@-40.708,-4.799 ccw(c-41.122,-4.344) -40.507,-4.373 ; v1@-40.707,-4.798 ccw(c-41.182,-4.323) -40.51,-4.323 ; v1@-40.707,-4.763 cw(c-41.182,-5.238) -40.51,-5.238 ; v1@-40.702,-4.77 cw(c-41.224,-5.022) -40.677,-5.212 ; v1@-40.668,3.101 ccw(c-40.823,3.37) -40.524,3.29 ; v1@-40.659,3.135 cw(c-40.928,2.98) -40.628,2.9 ; -41.536,-8.111 -40.51,-8.111 -40.51,3.339
  Top Layer w1: C14.1@-55.636,22.347 cw(c-56.319,21.665) -55.353,21.665 cw(c-54.387,21.665) C14.1@-55.07,22.347 ; C14.1@-55.353,22.63 -55.353,-1.394 -53.419,-3.329 -51.764,-3.329 ; v1(-49.977,-1.751) -50.449,-2.223 ; -49.484,3.084 -50.449,3.084 ; -49.228,-5.173 -49.581,-4.82 -50.368,-4.032 ; T1.6@-48.699,-3.834 ccw(c-49.581,-4.35) -49.581,-3.329 ; T1.6@-48.699,-2.823 cw(c-49.581,-2.307) -49.581,-3.329 ; T1.6@-48.544,-4.036 ccw(c-50.251,-5.743) -50.251,-3.329 ccw(c-50.251,-0.914) T1.6@-48.544,-2.622 ; -45.387,-6.769 -50.368,-6.769 ; v1@-44.121,-6.345 -45.133,-6.345 -50.368,-6.345 ; -51.764,-3.329 -51.554,-3.329 ; -51.764,-3.329 -50.935,-4.158 ; -51.554,-3.329 -50.935,-2.709 ; -51.554,-3.329 -51.072,-3.329 ; -51.072,-3.329 -50.935,-3.466 ; -51.072,-3.329 -50.935,-3.329 ; -50.935,-4.158 -50.935,-3.466 ; -50.935,-4.158 -50.935,-6.769 -50.368,-6.769 ; -50.935,-3.466 -50.368,-4.032 ; -50.935,-3.466 -50.935,-3.329 ; -50.935,-3.329 -49.581,-3.329 ; -50.935,-3.329 -50.935,-2.709 ; -50.935,-2.709 -50.449,-2.223 ; -50.935,-2.709 -50.935,3.084 -50.449,3.084 ; -50.449,-2.223 -50.449,3.084 ; -50.368,-6.769 -50.368,-6.345 ; -50.368,-6.345 -50.368,-4.032
  Top Layer w2: -49.581,-5.904 cw(c-47.481,-5.904) T1.6@-47.768,-3.824 ; -49.581,-3.624 cw(c-42.712,-3.624) T1.7@-47.489,1.312 ; -49.581,-3.578 cw(c-47.831,-3.578) -47.87,-1.829 ; -49.581,-2.739 ccw(c-47.246,-2.739) -48.897,-4.389 ; -49.581,2.09 ccw(c-42.418,2.09) T1.6@-47.483,-2.975 ; -49.228,-5.173 -47.836,-5.173 ; T1.7@-48.326,1.571 ccw(c-49.581,1.316) -49.581,2.596 ; T1.7@-48.19,1.318 cw(c-53.782,-4.274) -45.874,-4.274 ; T1.6@-48.189,-2.974 ccw(c-53.731,2.596) -45.874,2.596 ; T1.6@-47.881,-3.827 cw(c-48.077,-6.022) -45.874,-6.022 ; T1.7@-47.836,1.671 T1.6@-47.836,-3.329 -47.836,-5.173 ; -47.703,-1.835 cw(c-47.882,-3.835) v1@-45.874,-3.835 ; T1.7@-47.483,1.318 cw(c-44.397,-1.768) -44.397,2.596 ; -46.778,-4.392 ccw(c-48.944,-2.215) -45.874,-2.215 ; -42.997,-6.265 -42.874,-6.265 ; -42.915,-6.265 cw(c-42.915,-8.414) C8.2@-41.395,-6.894 ; -42.874,-4.289 ccw(c-38.79,-4.289) C8.2@-41.678,-7.177 ; -42.874,-1.382 cw(c-38.79,-1.382) C7.2@-41.678,1.505 ; C7.2@-41.552,1.165 cw(c-41.438,2.596) -42.874,2.596 ; C8.2@-41.392,-6.897 ccw(c-42.874,-8.317) -42.874,-6.265 ; C7.2@-41.343,1.415 ccw(c-42.874,1.013) -42.874,2.596 ; -49.581,2.596 -45.874,2.596 ; -49.581,2.596 -49.581,-3.329 -49.581,-4.82 -49.581,-5.223 -47.836,-5.223 ; -47.836,-5.223 -46.255,-5.223 -45.133,-6.345 -44.121,-7.357 ; -47.836,-5.223 -47.836,-5.173 ; -47.836,-5.173 -45.874,-5.173 ; -45.874,-5.173 -45.874,2.596 ; -45.874,-5.173 -44.121,-5.173 ; -45.874,2.596 ccw(c-45.874,1.032) -47.361,1.516 cw(c-45.874,1.032) -45.874,2.596 ; -45.874,2.596 -44.121,2.596 ; -44.121,-7.357 -44.121,-6.345 -44.121,-5.173 ; -44.121,-7.357 -41.536,-7.357 C8.2@-41.536,-7.036 C7.2@-41.536,1.364 -41.536,2.596 -42.874,2.596 ; -44.121,-5.173 -44.121,2.596 ; -44.121,2.596 -42.874,2.596 ; -42.874,-6.265 -42.874,2.596 ; -49.581,-5.623 cw(c-47.786,-5.623) -47.825,-3.829 ccw(c-47.786,-5.623) -49.581,-5.623 ; T1.6@-47.336,-3.329 ccw(c-45.374,-3.329) -46.762,-4.717 cw(c-45.374,-3.329) T1.6@-47.336,-3.329
  POWER w0.16: v1@-27.369,-14.253 ccw(c-27.617,-14.006) -27.267,-14.006 ccw(c-26.917,-14.006) v1@-27.164,-14.253 ; v1@-27.359,-4.086 cw(c-27.582,-4.309) -27.267,-4.309 ; v1(-27.267,-14.356) -27.267,-3.994 v1(-27.257,-3.984) ; -27.267,-4.359 cw(c-26.882,-4.359) v1@-27.154,-4.086
  GND w0.5: -44.594,-6.624 -44.108,-7.109 ; v1@-44.194,-6.488 ccw(c-43.741,-6.742) -44.108,-7.109 ; -36.853,-8.011 -36.55,-8.314 ; -35.803,-9.554 -35.803,-9.061 -36.536,-8.328 -36.55,-8.314 ; -44.108,-7.109 -44.108,-8.28 -44.075,-8.314 -39.697,-8.314 -36.55,-8.314
  GND w1: -50.18,1.951 -50.18,3.348 ; -44.427,-6.297 -45.202,-6.297 ; -39.697,-8.314 -39.475,-8.536 ; -36.871,-2.647 -36.288,-2.647 -35.494,-3.44 ; -36.536,-8.314 -36.536,-8.328 -36.536,-8.536 -38.462,-8.536 ; -36.529,-10.911 -36.529,-10.469 -38.462,-8.536 ; -36.512,-11.499 -39.475,-8.536 ; -35.897,-3.717 -35.897,-4.28 -33.175,-7.001 ; -35.253,-3.682 -35.494,-3.44 ; -32.896,-6.039 -35.494,-3.44 ; -50.18,3.348 -35.494,3.348 -35.494,-3.44 ; -50.18,3.348 -50.621,3.348 -50.621,-6.297 -45.202,-6.297 ; -45.202,-6.297 -45.202,-8.536 -39.475,-8.536 ; -39.475,-8.536 -38.462,-8.536
  Bottom Layer w0.16: C75.1@-29.04,-21.525 ccw(c-29.758,-20.807) -28.743,-20.807 ccw(c-27.728,-20.807) C75.1@-28.445,-21.525 ; C75.1@-28.927,-21.638 ccw(c-29.371,-21.194) -28.743,-21.194 ccw(c-28.114,-21.194) C75.1@-28.559,-21.638 ; C75.1@-28.83,-21.706 ccw(c-29.041,-21.495) C75.1@-28.743,-21.495 ; C75.1@-28.743,-21.822 -28.743,-15.02 -28.078,-14.356 v1(-27.267,-14.356) ; C75.1@-28.743,-21.422 ccw(c-28.341,-21.422) C75.1@-28.625,-21.706 ; v1@-27.369,-14.459 ccw(c-27.617,-14.706) -27.617,-14.356 ccw(c-27.617,-14.006) v1@-27.369,-14.253 ; v1(-27.257,-3.984) -23.99,-3.984 -23.513,-3.506 v1(-23.513,-2.325) ; v1@-27.154,-4.086 cw(c-26.907,-4.334) -26.907,-3.984 cw(c-26.907,-3.634) v1@-27.154,-3.881 ; v1@-23.615,-2.428 cw(c-23.863,-2.675) -23.513,-2.675 cw(c-23.163,-2.675) v1@-23.41,-2.428
  Bottom Layer w0.2: v1@-24.732,-14.249 cw(c-24.952,-14.469) -24.641,-14.469 ; -24.641,-14.455 cw(c-24.348,-14.455) v1@-24.555,-14.249 ; v1@-24.641,-14.177 -24.641,-18.506 -24.162,-18.985 -4.948,-18.985 -4.237,-19.696 -4.237,-33.613 -4.884,-34.261 C62.2@-6.837,-34.261 ; C62.2@-7.022,-34.136 ccw(c-6.722,-33.837) C62.2@-6.722,-34.261 ; C62.2@-6.881,-33.995 ccw(c-6.239,-33.354) C62.2@-6.239,-34.261 ; C62.2@-6.739,-33.854 ccw(c-5.756,-32.871) -5.756,-34.261 ; C62.2@-6.524,-34.574 cw(c-5.769,-35.329) -5.769,-34.261 cw(c-5.769,-33.192) C62.2@-6.524,-33.948 ; C62.2@-6.383,-34.715 cw(c-5.286,-35.812) -5.286,-34.261 cw(c-5.286,-32.71) C62.2@-6.383,-33.806
  Bottom Layer w0.5: -43.228,-7.752 ccw(c-43.228,-5.552) C8.2@-41.574,-7.003 ; v1(-42.252,-20.18) -42.252,-14.925 -42.649,-14.528 v1(-45.216,-14.528) -45.216,-8.636 -44.332,-7.752 ; -42.124,-7.752 ccw(c-42.124,-6.52) C8.2@-41.198,-7.332 ; C8.2@-41.95,-6.673 cw(c-44.332,-4.584) -44.332,-7.752 ; C8.2@-41.536,-7.036 -42.253,-7.752 -44.332,-7.752
  Bottom Layer w1: v1(-35.537,-21.876) v1(-35.537,-26.029) v1(-33.468,-26.029) C77.1@-31.11,-26.029
  other v1: -1.349,-41.856 -14.346,-41.765 -11.73,-41.666 -5.194,-41.252 -61.545,-41.129 -52.273,-41.095 -46.83,-41.004 -1.349,-41.006 -14.346,-40.915 -11.73,-40.815 -38.508,-40.569 -37.657,-40.569 -36.807,-40.569 -35.957,-40.569 -5.194,-40.401 -1.349,-40.155 -14.346,-40.065 -11.73,-39.965 -2.696,-39.58 -5.194,-39.551 -1.349,-39.305 -9.516,-39.266 -8.666,-39.266 -7.816,-39.266 -6.965,-39.266 -14.346,-39.214 -11.73,-39.115 -2.696,-38.73 -5.194,-38.701 -1.331,-38.25 -2.696,-37.88 -1.331,-37.4 -11.179,-37.237 -5.68,-37.237 -2.696,-37.029 -60.591,-36.832 -1.331,-36.55 -1.331,-35.7 -6.839,-34.648 -14.526,-34.097 -6.828,-33.942 -46.83,-33.897 -14.526,-33.247 -5.579,-33.209 -6.916,-32.869 -18.127,-32.789 -20.222,-32.534 -7.725,-32.407 -14.526,-32.396 -19.093,-32.37 -5.579,-32.359 -35.923,-31.738 -16.151,-31.711 -19.093,-31.519 -5.579,-31.509 -14.67,-31.479 -7.907,-31.471 -5.579,-30.658 -7.907,-30.621 -5.579,-29.808 -6.204,-29.676 -7.429,-29.204 -5.579,-28.958 -6.204,-28.826 -5.579,-28.108 -7.901,-28.024 -6.204,-27.976 -5.579,-27.257 -7.916,-27.241 -7.04,-27.23 -6.204,-27.125 -7.939,-26.412 -5.579,-26.407 -6.816,-26.133 -34.121,-26.081 -34.935,-26.032 -7.924,-25.599 -5.579,-25.557 -6.8,-25.279 -35.531,-25.124 -5.579,-24.707 -7.917,-24.675 -35.531,-24.274 -26.212,-24.145 -6.605,-24.069 -5.579,-23.856 -7.917,-23.825 -26.212,-23.562 -35.531,-23.424 -5.579,-23.006 -26.212,-22.979 -35.531,-22.574 -29.376,-22.479 -28.757,-22.479 -28.138,-22.479 -27.519,-22.479 -26.901,-22.479 -26.212,-22.403 -30.556,-22.383 -5.579,-22.156 -7.917,-22.124 -26.212,-21.813 -29.34,-21.808 -28.728,-21.808 -28.116,-21.808 -27.504,-21.808 -26.892,-21.808 -30.556,-21.533 -5.579,-21.306 -6.259,-21.196 -7.529,-20.667 -5.579,-20.455 -6.259,-20.345 -5.579,-19.605 -6.259,-19.495 -43.288,-6.577 -44.172,-6.5 -42.155,-5.864 -45.399,-5.792 -43.288,-5.727 -44.172,-5.65 -48.859,-5.414 -48.009,-5.414 -47.159,-5.414 -46.309,-5.414 -50.009,-5.341 -42.155,-5.013 -45.399,-4.942 -43.288,-4.877 -44.172,-4.799 -40.725,-4.78 -46.03,-4.62 -50.009,-4.491 -42.155,-4.163 -45.399,-4.091 -43.288,-4.027 -44.172,-3.949 -46.051,-3.829 -50.009,-3.64 -42.155,-3.313 -45.399,-3.241 -43.288,-2.869 -44.266,-2.837 -50.009,-2.79 -42.17,-2.682 -43.288,-2.019 -44.266,-1.987 -45.864,-1.891 -42.17,-1.832 -48.995,-1.666 -47.257,-1.382 -43.288,-1.168 -44.266,-1.137 -45.864,-1.041 -42.17,-0.982 -49.977,-0.901 -49.263,-0.789 -48.413,-0.789 -47.563,-0.789 -46.713,-0.789 -40.744,-0.797 -43.288,-0.318 -44.266,-0.286 -45.864,-0.191 -42.17,-0.131 -49.136,-0.105 -49.977,-0.051 -46.778,-0.07 -44.281,0.578 -45.864,0.66 -49.977,0.799 -44.281,1.428 -44.281,2.278 -44.281,3.129 -43.231,3.123 -42.381,3.123 -41.531,3.123 -40.681,3.123
I2C_SCL: R26.1 U5.6 U6.14 U12.10 U13.6 | length 77.1
  Top Layer w0.16: v1(-29.544,-26.956) -28.811,-26.222 U13.6@-27.978,-26.222 ; v1@-29.544,-26.811 ccw(c-29.544,-26.461) -29.296,-26.708 ccw(c-29.049,-26.956) v1@-29.399,-26.956 ; U6.14@-26.589,6.512 cw(c-26.692,6.409) -26.547,6.409 cw(c-26.402,6.409) U6.14@-26.504,6.512 ; -26.547,4.827 ccw(c-25.794,4.827) R26.1@-26.326,4.295 ; -26.547,5.213 ccw(c-25.408,5.213) R26.1@-26.213,4.408 ; -26.547,5.6 ccw(c-25.021,5.6) R26.1@-26.1,4.521 ; U6.14@-26.547,6.864 -26.547,4.686 ; R26.1@-26.424,4.388 ccw(c-26.842,4.391) -26.547,4.686 ; R26.1@-26.249,4.576 cw(c-26.278,4.955) -26.547,4.686 ; R26.1@-26.1,4.24 cw(c-25.776,3.915) -25.776,4.374 cw(c-25.776,4.833) R26.1@-26.1,4.508 ; v1@-24.354,3.954 ccw(c-24.704,3.954) -24.456,4.201 ccw(c-24.209,4.449) v1@-24.209,4.099 ; v1(-24.209,3.954) -24.629,4.374 R26.1@-26.234,4.374 -26.547,4.686 ; v1@-14.402,-10.364 ccw(c-14.649,-10.116) -14.299,-10.116 ccw(c-13.949,-10.116) v1@-14.197,-10.364 ; U12.10@-14.349,-9.887 cw(c-14.468,-10.006) -14.299,-10.006 cw(c-14.13,-10.006) U12.10@-14.25,-9.887 ; v1@-14.304,-10.471 v1(-14.299,-10.466) U12.10@-14.299,-9.337
  POWER w0.16: v1(-29.544,-26.956) -28.975,-26.387 -24.77,-26.387 -23.475,-25.091 -23.475,-18.821 -22.621,-17.967 -17.382,-17.967 v1(-17.362,-17.948) ; v1@-29.544,-26.811 ccw(c-29.544,-26.461) -29.296,-26.708 ccw(c-29.049,-26.956) v1@-29.399,-26.956 ; v1@-24.311,3.851 cw(c-24.559,3.604) -24.209,3.604 cw(c-23.859,3.604) v1@-24.106,3.851 ; v1(-24.209,3.954) -24.209,-4.691 -23.468,-5.432 -15.841,-5.432 -14.285,-6.987 -14.285,-10.452 v1(-14.299,-10.466) ; -17.76,-17.967 ccw(c-17.76,-17.55) v1@-17.465,-17.845 ; -17.665,-17.967 cw(c-17.665,-18.25) v1@-17.465,-18.05 ; v1@-14.402,-10.364 ccw(c-14.683,-10.083) -14.285,-10.083 ; -14.285,-10.15 ccw(c-13.983,-10.15) v1@-14.197,-10.364
  GND w0.16: v1(-17.362,-17.948) -15.179,-17.948 -14.299,-17.068 v1(-14.299,-10.466) ; v1@-17.26,-18.05 cw(c-17.012,-18.298) -17.012,-17.948 cw(c-17.012,-17.598) v1@-17.26,-17.845 ; v1@-14.402,-10.569 cw(c-14.649,-10.817) -14.299,-10.817 cw(c-13.949,-10.817) v1@-14.197,-10.569
  Bottom Layer w0.16: v1(-14.299,-10.466) -14.256,-10.51 -8.999,-10.51 v1(-8.494,-10.005) ; v1@-14.197,-10.569 cw(c-14.054,-10.712) -14.054,-10.51 ; v1@-14.197,-10.364 ccw(c-13.844,-10.011) -13.844,-10.51 ; v1@-8.639,-10.005 cw(c-8.989,-10.005) -8.741,-10.253 cw(c-8.494,-10.5) v1@-8.494,-10.15
I2C_SDA: R27.1 U5.5 U6.13 U12.9 U13.5 | length 76.8
  Top Layer w0.16: v1@-29.555,-26.016 cw(c-29.087,-26.484) -29.087,-25.822 ; v1(-29.544,-26.027) -29.34,-25.822 ; v1@-29.523,-25.883 ccw(c-29.492,-25.67) -29.34,-25.822 ; v1@-29.519,-26.126 v1@-29.481,-26.089 ; v1@-29.441,-26.129 cw(c-28.701,-26.87) -28.701,-25.822 ; v1@-29.401,-26.006 cw(c-29.187,-25.975) -29.34,-25.822 ; U13.5@-27.978,-25.822 -29.34,-25.822 ; v1(-27.751,5.833) -27.739,5.822 -27.047,5.822 ; v1@-27.648,5.731 cw(c-27.428,5.511) -27.428,5.822 ; v1@-27.648,5.936 ccw(c-27.373,6.211) -27.373,5.822 ; R27.1@-27.479,4.374 -27.047,4.806 -27.047,5.822 ; R27.1@-27.479,4.577 ccw(c-27.479,5.066) -27.133,4.72 ; R27.1@-27.289,4.387 cw(c-26.861,4.387) -27.164,4.689 ; U6.13@-27.09,6.512 cw(c-27.192,6.409) -27.047,6.409 cw(c-26.902,6.409) U6.13@-27.005,6.512 ; U6.13@-27.047,6.864 -27.047,5.822 ; v1@-14.893,-8.062 cw(c-15.118,-8.287) -14.8,-8.287 ; U12.9@-14.849,-8.788 ccw(c-14.969,-8.668) -14.8,-8.668 ccw(c-14.631,-8.668) U12.9@-14.75,-8.788 ; U12.9@-14.8,-9.337 -14.8,-7.968 v1(-14.79,-7.959) ; -14.8,-8.331 cw(c-14.418,-8.331) v1@-14.688,-8.062
  POWER w0.16: v1(-29.544,-26.027) -25.011,-26.027 -23.91,-24.926 -23.91,-18.612 -22.614,-17.315 v1(-16.59,-17.315) ; v1@-29.441,-26.129 cw(c-29.194,-26.377) -29.194,-26.027 cw(c-29.194,-25.677) v1@-29.441,-25.924 ; v1@-27.751,5.688 cw(c-27.751,5.338) -27.503,5.586 cw(c-27.256,5.833) v1@-27.606,5.833 ; v1(-27.751,5.833) -26.549,4.632 -25.151,4.632 -24.823,4.304 -24.823,-4.743 -23.711,-5.856 -15.926,-5.856 -14.79,-6.991 v1(-14.79,-7.959) ; v1@-16.693,-17.418 ccw(c-16.94,-17.665) -16.94,-17.315 ccw(c-16.94,-16.965) v1@-16.693,-17.213 ; v1@-14.893,-7.856 ccw(c-15.14,-7.609) -14.79,-7.609 ccw(c-14.44,-7.609) v1@-14.688,-7.856
  GND w0.16: v1(-16.59,-17.315) -15.965,-17.315 -15.457,-16.807 -15.457,-8.183 -15.234,-7.959 v1(-14.79,-7.959) ; v1@-16.487,-17.418 cw(c-16.24,-17.665) -16.24,-17.315 cw(c-16.24,-16.965) v1@-16.487,-17.213 ; v1@-14.893,-8.062 ccw(c-15.14,-8.309) -15.14,-7.959 ccw(c-15.14,-7.609) v1@-14.893,-7.856
  Bottom Layer w0.16: v1@-14.893,-8.062 cw(c-15.14,-8.309) -14.79,-8.309 cw(c-14.44,-8.309) v1@-14.688,-8.062 ; v1(-14.79,-7.959) -14.79,-8.849 -13.635,-10.005 v1(-9.764,-10.005) ; v1@-9.866,-10.108 ccw(c-10.114,-10.355) -10.114,-10.005 ccw(c-10.114,-9.655) v1@-9.866,-9.902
